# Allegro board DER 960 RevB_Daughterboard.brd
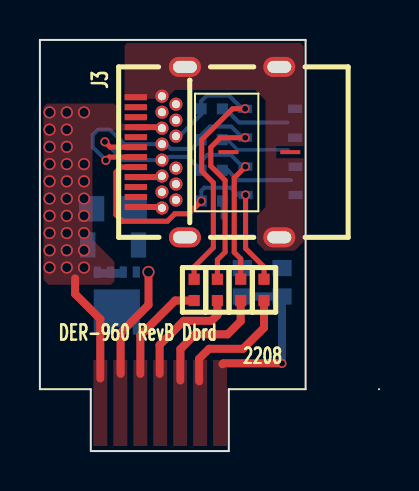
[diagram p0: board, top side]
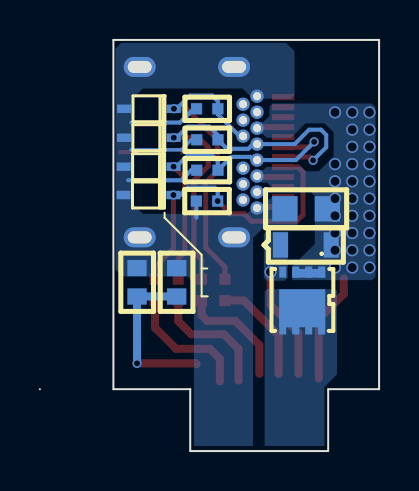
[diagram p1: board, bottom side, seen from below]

Outline 17 x 20.6 mm; copper layers: TOP, BOTTOM. Coordinates in mm from the lower left corner of the outline.
Outline path: 2.55,0 2.55,3.1 0,3.1 0,20.6 13.31,20.6 13.31,3.1 9.46,3.1 9.46,0 2.6,0 ; 17,3.1 17,3.1

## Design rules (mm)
constraint set DEFAULT: min track width 0.17

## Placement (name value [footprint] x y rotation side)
C32  2.2 uF  [PISMC0805]  4.72 12.14 180 bottom
C35  560 pF  [PISMR0402]  8.07 15.6 0 bottom
C36  560 pF  [PISMR0402]  9.16 12.52 180 bottom
C37  560 pF  [PISMR0402]  8.08 17.15 0 bottom
C38  560 pF  [PISMR0402]  9.14 14.07 180 bottom
D8  BAV21WS-7-F  [PISMSOD323]  4.94 10.33 180 bottom
D10  MM3Z24VC  [PISMSOD323F]  10.29 15.7 0 bottom
D11  MM3Z24VC  [PISMSOD323F]  10.31 12.83 0 bottom
D12  MM3Z24VC  [PISMSOD323F]  10.28 17.15 0 bottom
D13  MM3Z24VC  [PISMSOD323F]  10.3 14.25 0 bottom
J3  CON24_USB_C  [PI_CONN_USBC_WURTH1]  6.82 14.98 90 top
NOREF  -  []  -154.77 -30.84 0 top
NOREF#2  -  []  2.55 0 90 top
NOREF#3  -  []  13.31 3.1 90 top
NOREF#4  -  []  0 20.6 0 top
NOREF#5  -  []  -228.6 -134.68 0 top
NOREF#6  -  []  0 3.1 0 top
NOREF#7  -  []  9.46 3.1 0 top
NOREF#8  -  []  2.6 0 0 top
Q7  AON7318  [PISMDFN_EP3_3X3_3]  2.88 8.97 0 bottom
R44  82 k  [PISMR0603]  10.14 9.17 270 bottom
R45  3.3  [PISMR0402]  8.89 8.61 270 top
R46  22  [PISMR0402]  11.23 8.61 270 top
R47  22  [PISMR0402]  7.73 8.61 270 top
R48  3.3  [PISMR0402]  10.06 8.61 270 top
RT1  100 k  [PISMR0603]  12.13 7.75 90 bottom

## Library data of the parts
C32 = CAP NP
C35-C38 = CAP NP: alternate symbols: (pismr0402_1,cc0402); room: 6
D8 = DIODE: room: 3
D10-D13 = DIODE_ZENER: room: 6
J3 = CON24_USBgjc1_0: room: 6
Q7 = FET_N_SGD_123_4_5678
R44 = R: room: 4
R45-R48 = R: room: 6
RT1 = THERMISTOR: room: 6

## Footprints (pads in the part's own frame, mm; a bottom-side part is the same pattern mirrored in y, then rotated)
PI_CONN_USBC_WURTH1
  round 0.66 hole 0.406: (-2,0.7) (2,0.7) B1(2.8,0.7) B2(2.4,0) B3(1.6,0) B4(1.2,0.7) B5(0.8,0) B6(0.4,0.7) B7(-0.4,0.7) B8(-0.8,0) B9(-1.2,0.7) B10(-1.6,0) B11(-2.4,0) B12(-2.8,0.7)
  rect 0.305x1.118 smd: A1(-2.75,2.01) A2(-2.25,2.01) A3(-1.75,2.01) A4(-1.25,2.01) A5(-0.75,2.01) A6(-0.25,2.01) A7(0.25,2.01) A8(0.75,2.01) A9(1.25,2.01) A10(1.75,2.01) A11(2.25,2.01) A12(2.75,2.01)
  oval 1x1.6 hole 0.6x1.2: S1(-4.27,-0.45) S2(-4.27,-5.18) S3(4.27,-5.18) S4(4.27,-0.45)
PISMC0805
  rect 1.27x1.27 smd: 1(0,0) 2(2.134,0)
PISMDFN_EP3_3X3_3
  rect 0.356x0.559 smd: 1(0,0) 2(0.65,0) 3(1.3,0) 4(1.95,0) 5(1.95,2.85) 6(1.3,2.85) 7(0.65,2.85) 8(0,2.85)
PISMR0402
  rect 0.559x0.559 smd: 1(0,0) 2(1.067,0)
PISMR0603
  rect 0.813x0.965 smd: 1(0,0) 2(1.422,0)
PISMSOD323
  rect 0.762x1.27 smd: 1(0,0) 2(2.54,0)
PISMSOD323F
  rect 0.7x0.42 smd: 1(0,0) 2(2.5,0)

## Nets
VBUS_OUT: C32.2 D8.2 J3.A4 J3.A9 J3.B4 J3.B9 Q7.1 Q7.2 Q7.3(S3)
RTN: C32.1 C35.2 C36.1 C37.2 C38.1 D10.2 D11.2 D12.2 D13.2 J3.A1 J3.A12 J3.B1 J3.B12 J3.S1 J3.S2 J3.S3 J3.S4 R44.1 RT1.2
VOUT: Q7.5 Q7.6 Q7.7 Q7.8
N12978385: C36.2 D11.1 J3.A5 R46.1
N12978393: C38.2 D13.1 J3.A7 J3.B7 R48.1
N12978617: C35.1 D10.1 J3.A6 J3.B6 R45.1
N12978703: C37.1 D12.1 J3.B5 R47.1
N12982116: D8.1 Q7.4
N13110214: R44.2 RT1.1
N13120477: R46.2
N13120713: R48.2
N13120918: R45.2
N13120931: R47.2

Pads without a net: J3 A2 A3 A8 A10 A11 B2 B3 B8 B10 B11

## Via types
v1: diameter 0.457, hole 0.305, TOP to BOTTOM, 8 vias
v2: diameter 0.61, hole 0.457, TOP to BOTTOM, 29 vias

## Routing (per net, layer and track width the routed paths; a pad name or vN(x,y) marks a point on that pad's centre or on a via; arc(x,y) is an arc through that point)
VBUS_OUT: length 8.2
  TOP w0.3: J3.A9 6,16.23 arc(6.06,16.22) J3.B4 ; J3.B9 6.07,13.73 J3.A4
  TOP w0.4: 1.77,8.65 1.77,7.87 3.03,6.61 3.03,3.64
  vias: v2(0.48,16.97) v2(0.48,16.1) v2(0.48,15.24) v2(0.48,14.38) v2(0.48,13.51) v2(0.48,12.65) v2(0.48,11.79) v2(0.48,10.92) v2(0.48,10.06) v2(0.48,9.2) v2(1.35,16.97) v2(1.35,16.1) v2(1.35,15.24) v2(1.35,14.38) v2(1.35,13.51) v2(1.35,12.65) v2(1.35,11.79) v2(1.35,10.92) v2(1.35,10.06) v2(1.35,9.2) v2(2.21,16.97) v2(2.21,14.38) v2(2.21,13.51) v2(2.21,12.65) v2(2.21,11.79) v2(2.21,10.92) v2(2.21,10.06) v2(2.21,9.2)
RTN: length 13.1
  TOP w0.3: J3.B12 6.07,12.23 J3.A1
  BOTTOM w0.17: 12.44,15.09 9.9,15.09 9.4,15.6 C35.2 ; 9.15,11.69 9.16,11.7 ; 9.63,16.81 9.81,16.63
  BOTTOM w0.203: 12.41,16.46 9.98,16.46 9.81,16.63 9.81,16.63 9.63,16.81 9.63,16.81 9.29,17.15 C37.2 ; 9.16,11.7 C36.1 ; C38.1 9.41,14.07 9.91,13.57 12.58,13.57
N12978385: length 15.6
  TOP w0.254: R46.1 11.23,9.23 10.31,10.15 v1(10.31,12.83) ; J3.A5 4.06,14.23 3.81,13.97 3.81,11.84 4.13,11.52 6.39,11.52 6.76,11.89 7.45,11.89 v1(8.09,12.52)
  BOTTOM w0.203: v1(10.31,12.83) 9.95,12.83 9.58,13.2 8.24,13.2 8.09,13.04 v1(8.09,12.52)
N12978393: length 16.3
  TOP w0.254: J3.A7 3.52,15.23 v1(3.26,15.49) ; v1(10.3,14.25) 9.74,13.69 9.74,9.96 10.06,9.63 R48.1
  BOTTOM w0.2: J3.B7 5.43,14.58 5.43,14.58 4.17,14.58 v1(3.26,15.49)
  BOTTOM w0.203: v1(10.3,14.25) 10.16,14.25 9.57,14.84 8.39,14.84 8.07,14.53 C38.2 7.41,14.74 6.46,14.74 6.3,14.58 J3.B7
N12978617: length 21.1
  TOP w0.254: R45.1 8.89,9.58 9.28,9.97 9.28,13.56 8.56,14.28 8.56,15.22 9.04,15.7 v1(10.29,15.7) ; v1(3.31,14.57) 3.47,14.73 J3.A6
  BOTTOM w0.2: J3.B6 4.23,15.38 3.51,16.1 2.91,16.1 2.65,15.84 2.65,15.22 v1(3.31,14.57)
  BOTTOM w0.203: J3.B6 6.32,15.38 6.55,15.14 7.62,15.14 C35.1 8.05,15.79 8.05,15.8 8.51,16.26 9.59,16.26 10.15,15.7 v1(10.29,15.7)
N12978703: length 15.4
  TOP w0.254: R47.1 7.73,9.23 8.69,10.19 8.69,13.44 8.11,14.03 8.11,15.6 9.65,17.15 v1(10.28,17.15)
  BOTTOM w0.203: v1(10.28,17.15) 10.14,17.15 9.48,17.81 8.36,17.81 8.08,17.53 C37.1 8.08,16.87 6.99,15.78 J3.B5
N12982116: length 5.7
  TOP w0.4: 4.04,3.87 4.04,5.92 5.44,7.32 v2(5.44,8.97)
N13110214: length 8.3
  TOP w0.4: 9.15,4.35 9.19,4.4 v1(12.13,4.4)
  BOTTOM w0.4: v1(12.13,4.4) RT1.1 R44.2
N13120477: length 6.4
  TOP w0.4: 7.98,3.49 7.98,4.63 8.48,5.12 10.18,5.12 11.23,6.18 R46.2
N13120713: length 6.2
  TOP w0.4: R48.2 10.06,6.51 9.4,5.85 7.78,5.85 7.04,5.11 7.04,3.54
N13120918: length 5.7
  TOP w0.4: 6,3.87 6,5.31 7.21,6.53 8.61,6.53 8.89,6.81 R45.2
N13120931: length 5.3
  TOP w0.4: R47.2 6.78,7.54 5.03,5.8 5.03,3.87

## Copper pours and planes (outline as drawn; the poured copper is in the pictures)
VBUS_OUT on TOP: 0.18,17.24 0.35,17.42 3.7,17.42 3.81,17.31 3.81,16.63 4.03,16.41 5.38,16.41 5.38,16.07 5.36,16.06 2.83,16.06 2.63,15.86 2.63,10.6 3.74,9.49 3.74,8.51 3.56,8.33 0.43,8.33 0.18,8.58
VBUS_OUT on TOP: 2.68,4.57 3.38,4.57 3.38,0.26 2.68,0.26
VBUS_OUT on BOTTOM: 0.18,8.73 0.18,17.24 0.35,17.41 0.35,17.42 5.34,17.42 5.49,17.27 5.49,16.79 5.8,16.49 6.23,16.49 6.38,16.34 6.38,16.01 6.25,15.88 5.82,15.88 5.64,15.7 4.41,15.7 3.7,16.42 2.73,16.42 2.28,15.96 2.28,14.76 3.02,14.02 3.69,14.02 3.91,14.23 5.64,14.23 5.8,14.08 5.8,14.08 6.23,14.08 6.41,13.9 6.41,13.65 6.2,13.44 5.61,13.44 5.23,13.06 3.5,13.06 3.22,12.78 3.22,10.37 4.35,9.25 4.35,8.56 0.36,8.56
RTN on TOP: 13.21,20.29 13.05,20.45 4.38,20.45 4.24,20.32 4.24,17.65 5.78,17.65 5.9,17.52 6.2,17.52 6.76,18.09 10.79,18.09 11.3,17.58 11.3,12.22 10.88,11.79 10.88,10.43 11.27,10.04 12.77,10.04 13.21,10.49
RTN on BOTTOM: 4.65,20.45 12.92,20.45 13.21,20.16 13.21,9.1 12.86,8.74 9.58,8.74 9.28,8.44 9.28,0.26 6.32,0.26 6.32,10.68 5.71,11.28 4.14,11.28 4.09,11.33 4.09,12.73 4.14,12.78 5.33,12.78 5.74,12.38 6.14,12.38 6.63,11.89 11.83,11.89 12.32,12.37 12.32,17.68 11.84,18.16 6.83,18.16 6.4,17.73 6.4,17.63 6.28,17.51 5.92,17.51 5.78,17.65 4.45,17.65 4.24,17.85 4.24,20.04 4.24,20.04
VOUT on BOTTOM (solid shape): 5.01,6.2 2.7,6.2 2.7,8.11 5.01,8.11
VOUT on BOTTOM: 5.74,0.26 2.74,0.26 2.74,3.22 2.11,3.84 2.11,8.03 2.19,8.11 5.45,8.11 5.63,8.11 5.74,8
N12982116 on TOP: 3.68,4.57 4.38,4.57 4.38,0.26 3.68,0.26
N12982116 on BOTTOM: 5.77,8.69 5.62,8.54 4.73,8.54 4.58,8.69 4.58,10.98 4.6,11 5.66,11 5.77,10.89
N13110214 on TOP: 8.68,4.57 9.38,4.57 9.38,0.26 8.68,0.26
N13120477 on TOP: 7.68,4.57 8.38,4.57 8.38,0.26 7.68,0.26
N13120713 on TOP: 6.68,4.57 7.38,4.57 7.38,0.26 6.68,0.26
N13120918 on TOP: 5.68,4.57 6.38,4.57 6.38,0.26 5.68,0.26
N13120931 on TOP: 4.68,4.57 5.38,4.57 5.38,0.26 4.68,0.26

Small or netless copper shapes (teardrops, artwork), in the pictures only: 2 on TOP, 1 on BOTTOM

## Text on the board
Ref Des/Silkscreen Top: DER-960 RevB Dbrd | 2208
User.10: SLOTS
User.11: NOTES: PLEASE DELETE PINS | 14.  FAB HOUSE LOGO,DATE CODE TO BE IN SILK SCREEN ONLY.DO NOT USE COPPER. | 13. MATERIAL FR4 COPPER 2oz THICKNESS 0.039"
User.14: FIGURE | FINISHED_SIZE | 12.0 | 16.0 | 18.0 | 47.24x23.62 | DRILL CHART: TOP to BOTTOM | ALL UNITS ARE IN MILS | TOLERANCE_DRILL | +3.0/-3.0 | PLATED | PLUGGED | QTY | 8 | 14 | 29 | 4 | 55 | TOTAL HOLES:
